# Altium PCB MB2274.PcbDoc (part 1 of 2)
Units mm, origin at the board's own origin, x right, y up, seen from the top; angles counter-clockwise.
Board outline 127 x 73 mm, 4 copper layers (Top Layer, Signal Layer 1, Signal Layer 2, Bottom Layer), stack 1.49 mm thick; 50 components, 79 nets, 284 pads, 1052 vias.
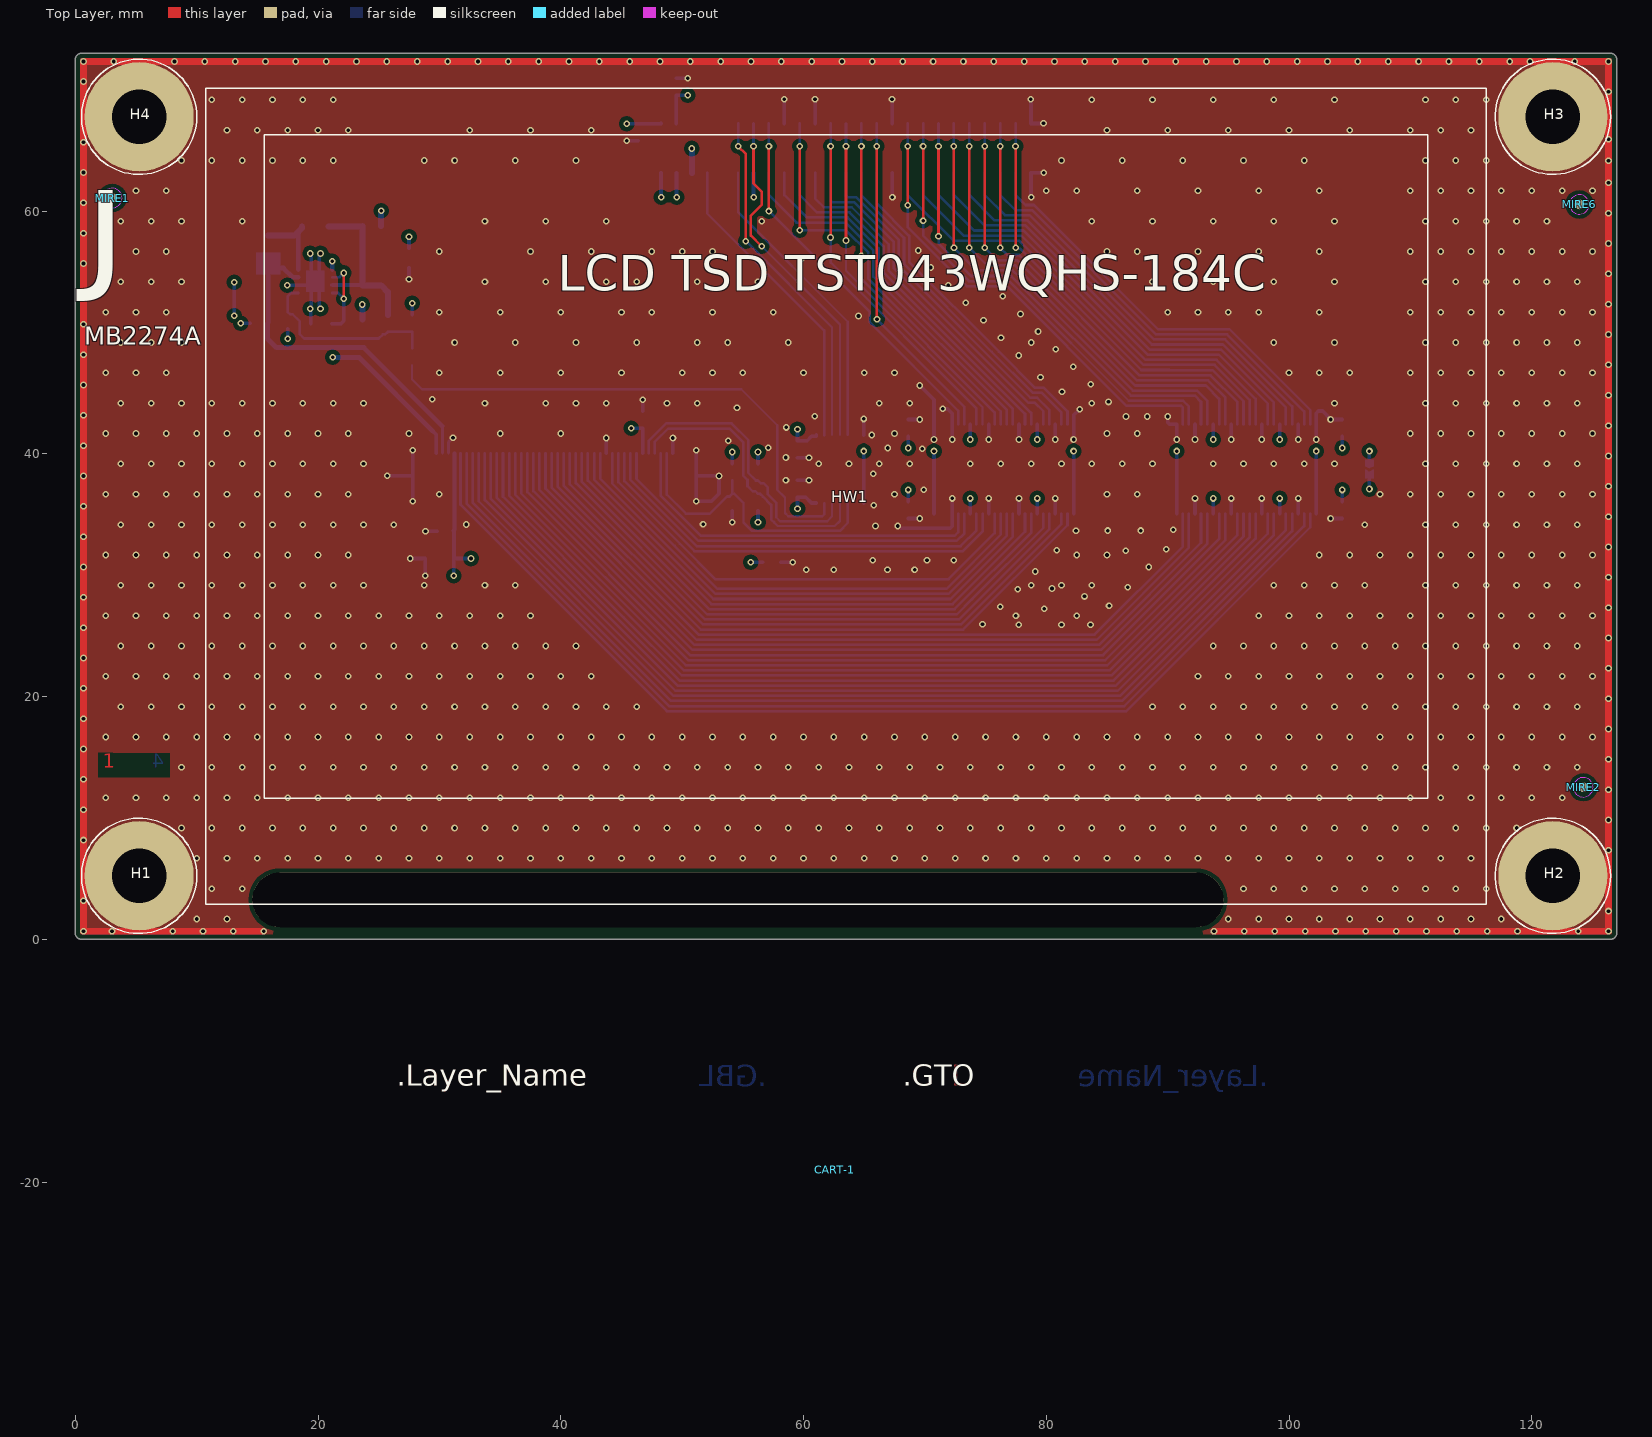
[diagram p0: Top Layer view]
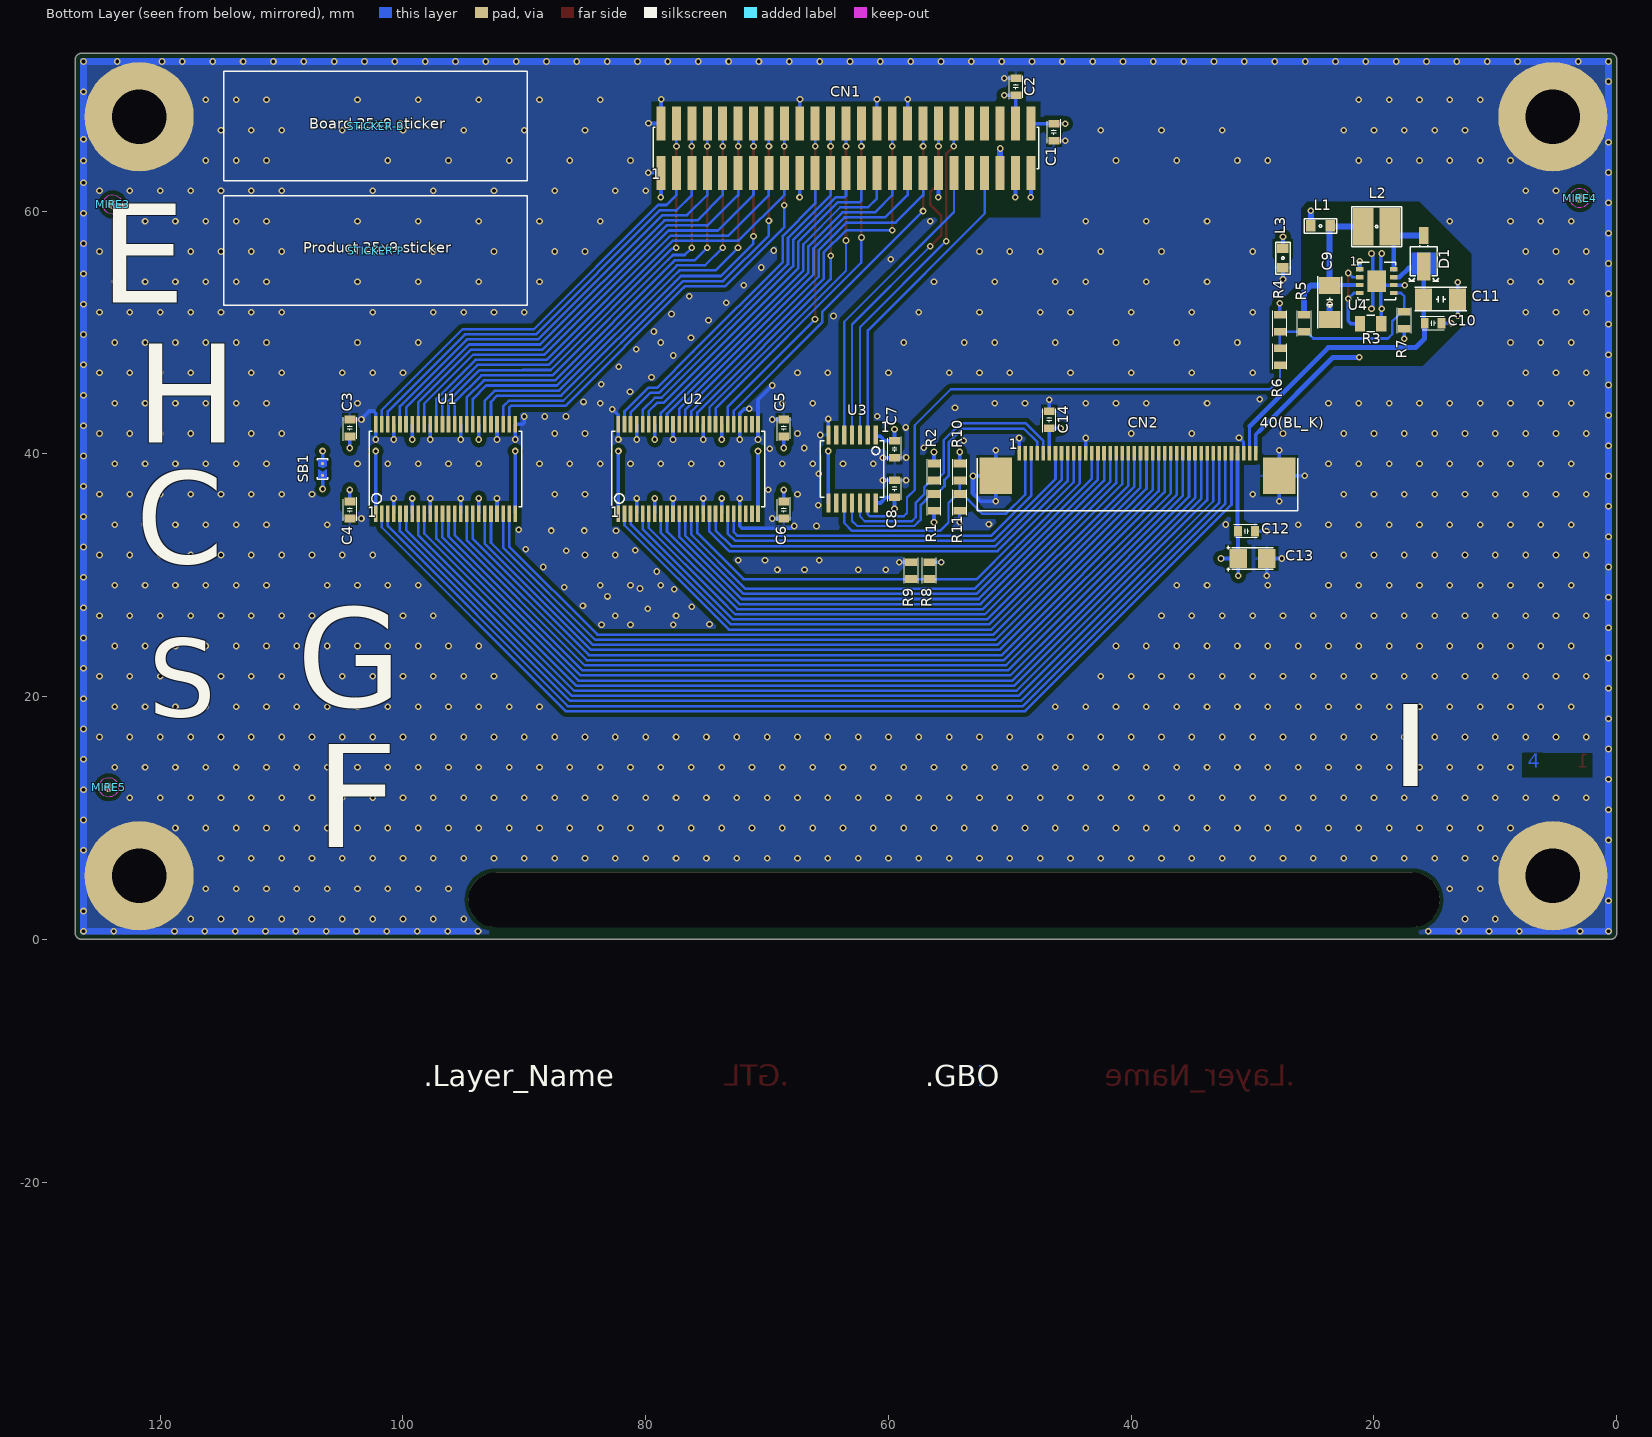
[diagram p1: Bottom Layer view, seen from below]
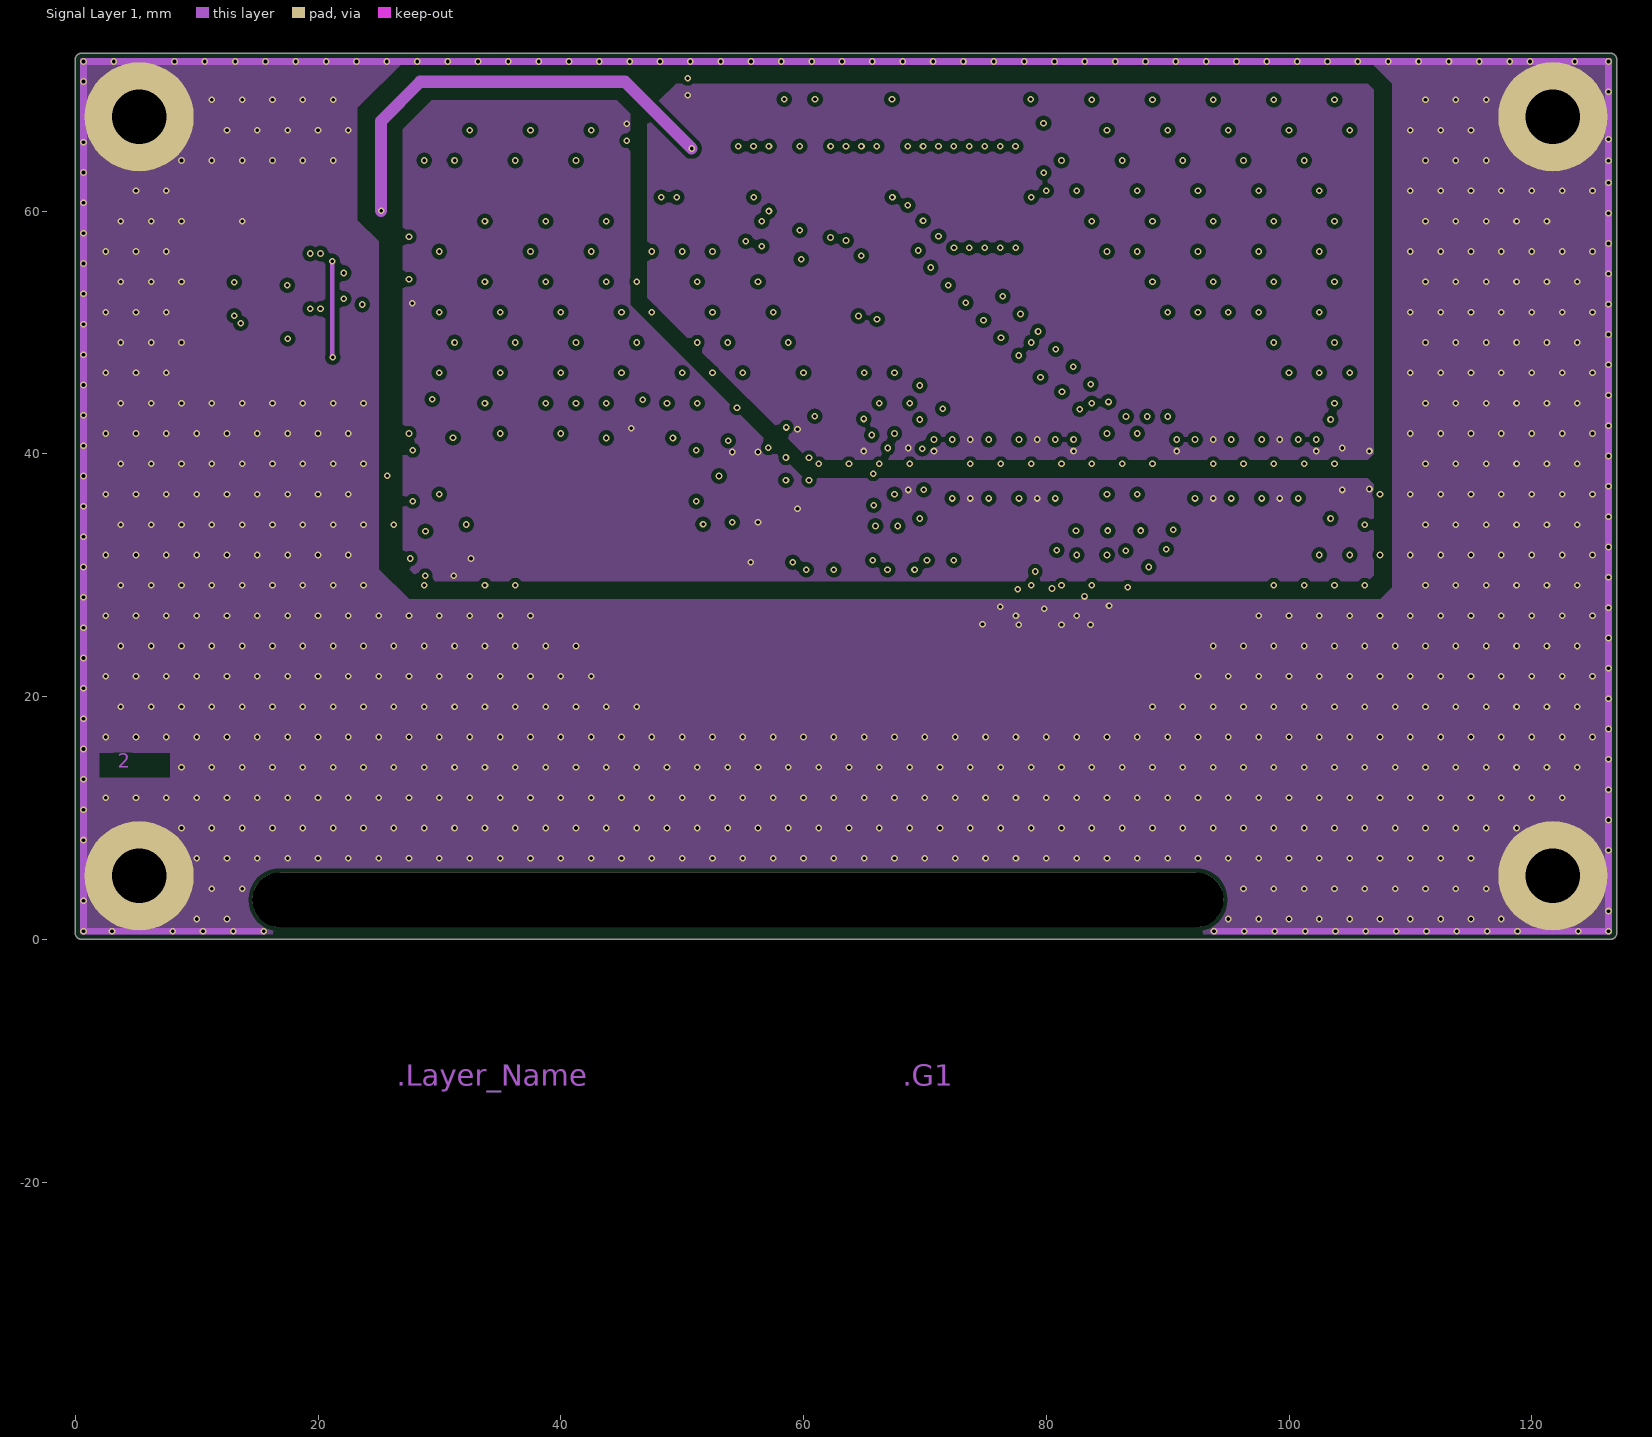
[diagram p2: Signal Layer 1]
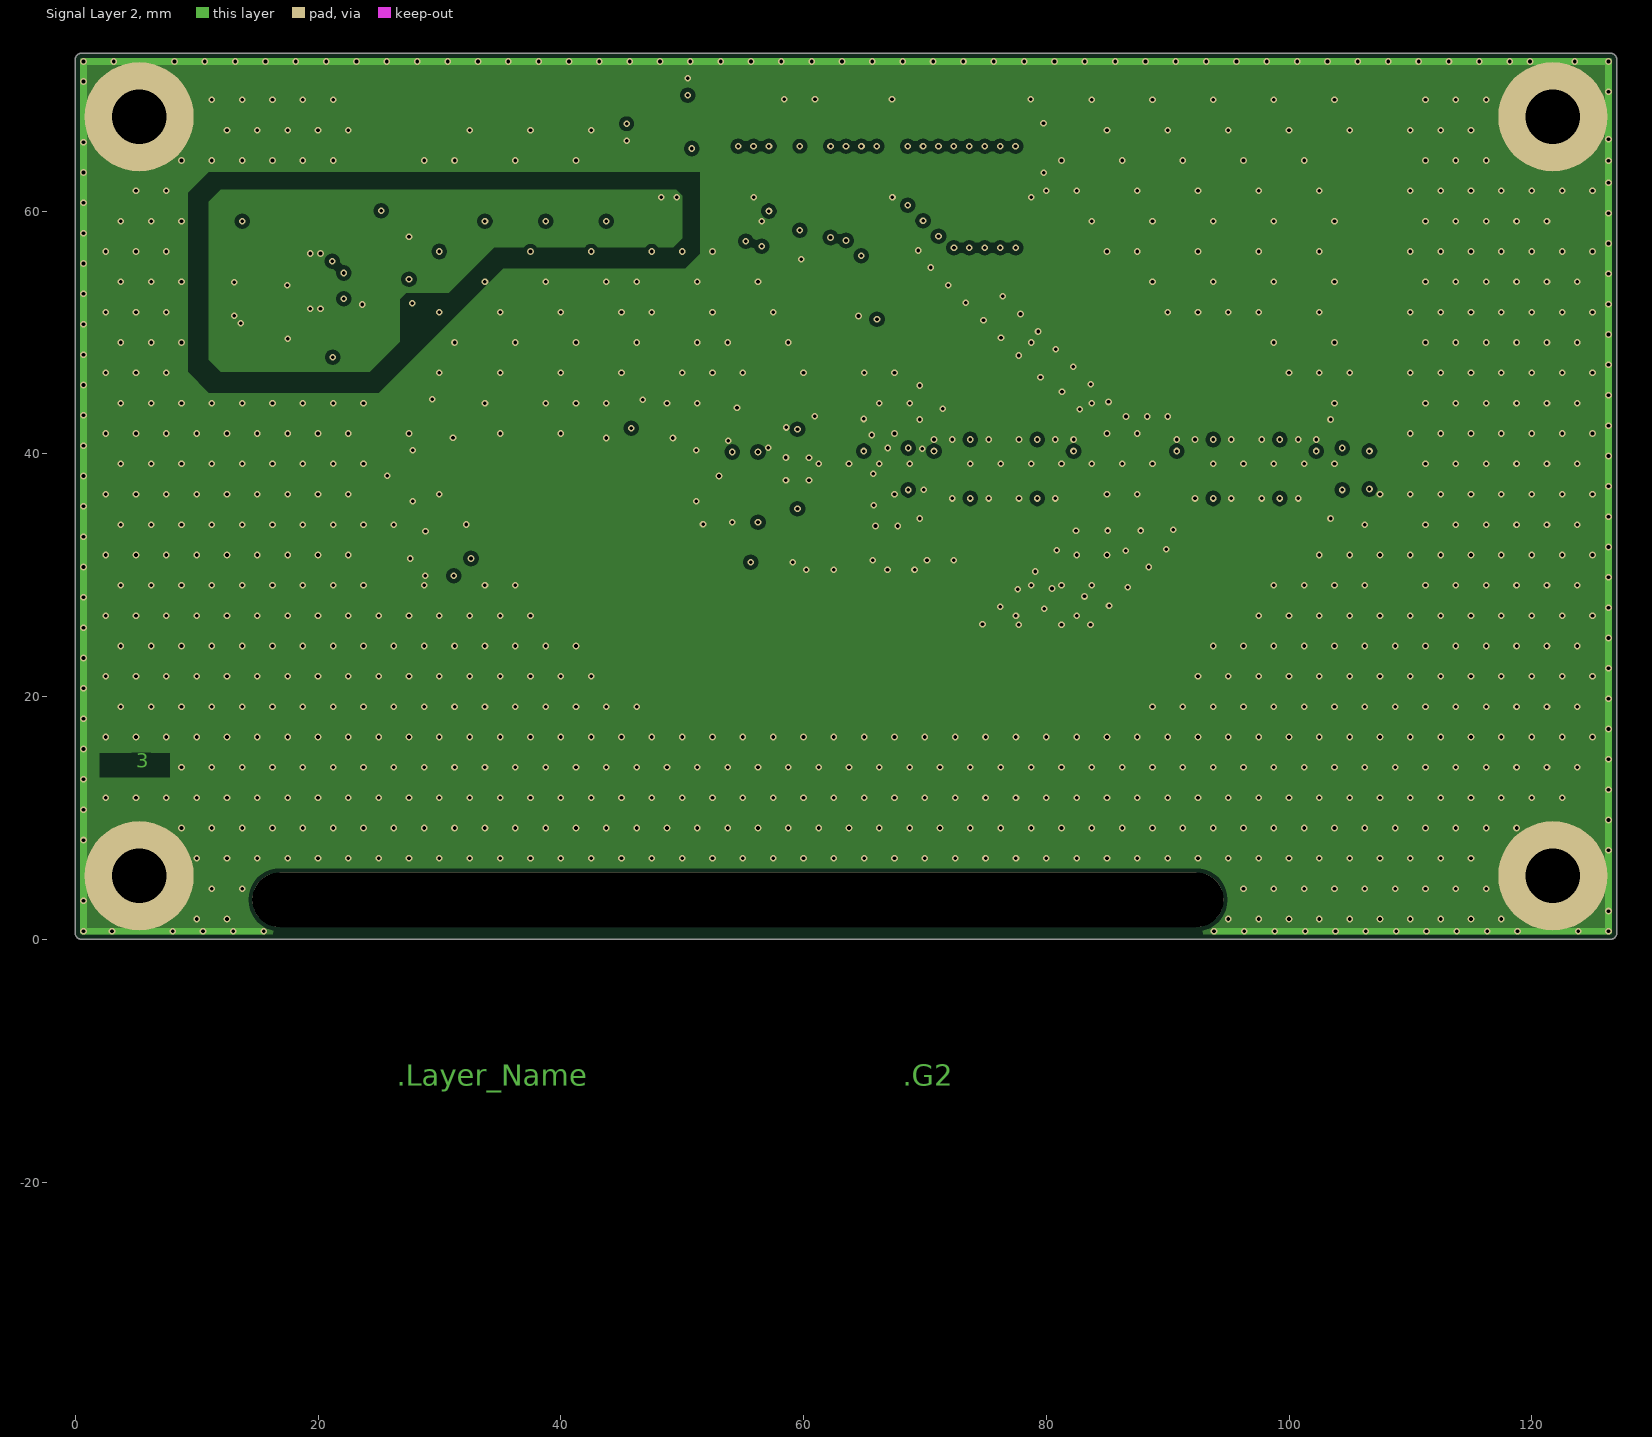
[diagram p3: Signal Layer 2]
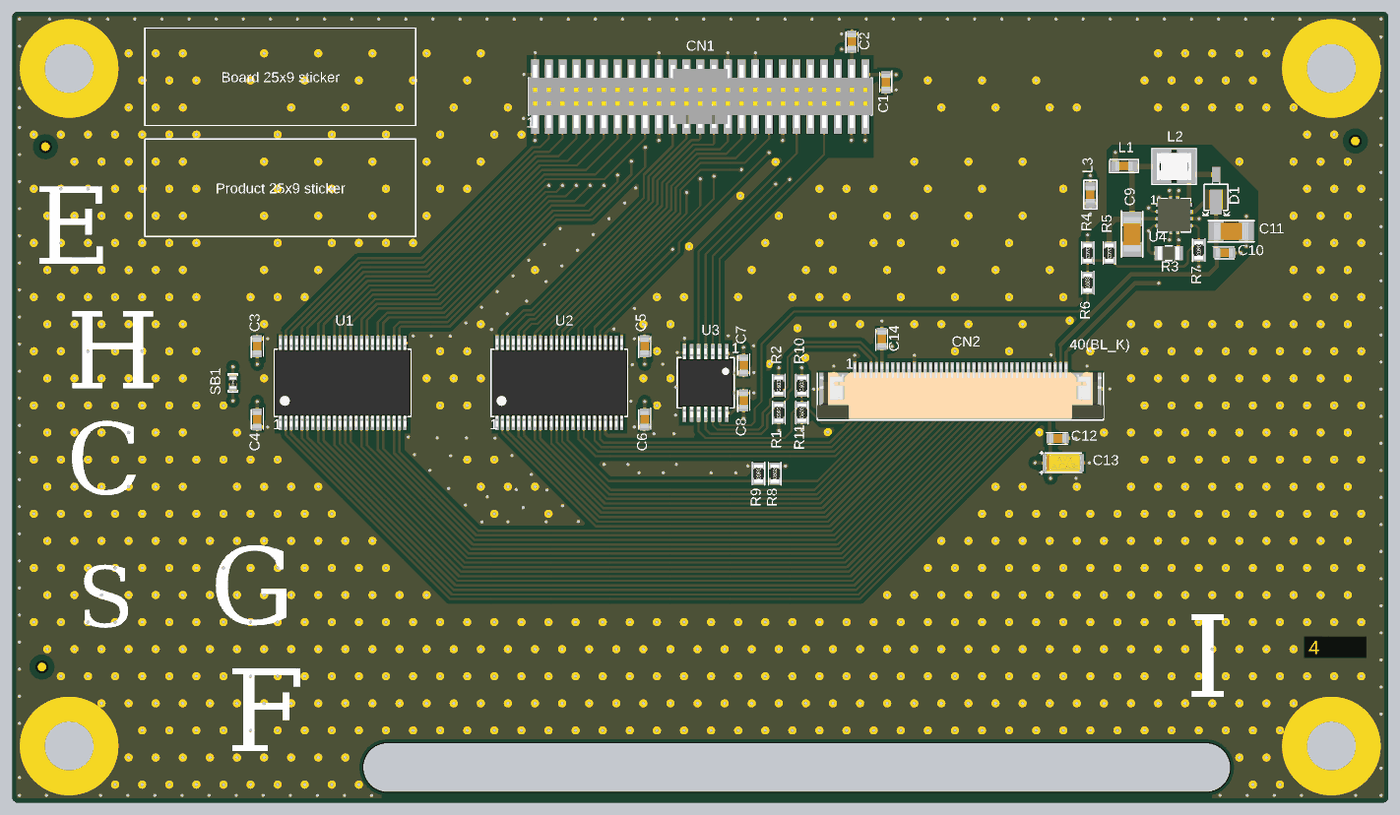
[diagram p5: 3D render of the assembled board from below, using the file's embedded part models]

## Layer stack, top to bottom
Top Solder: solder mask 0.15, Solder Resist, Dk 3.5
Top Layer: signal copper 0.035
Dielectric 1: prepreg 0.108, FR-4, Dk 3.8
Signal Layer 1: signal copper 0.035
Dielectric 2: core 1.134, FR-4, Dk 5.1
Signal Layer 2: signal copper 0.035
Dielectric 3: prepreg 0.108, FR-4, Dk 3.8
Bottom Layer: signal copper 0.035
Board Layer Stack Bottom Solder: solder mask 0.15, Solder Resist, Dk 3.5

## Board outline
0.5,0 cw(c0.5,0.5) 0,0.5 0,72.5 cw(c0.5,72.5) 0.5,73 126.5,73 cw(c126.5,72.5) 127,72.5 127,0.5 cw(c126.5,0.5) 126.5,0

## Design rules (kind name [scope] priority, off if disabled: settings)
BoardOutlineClearance [All] p1: gap=0.4 ignorepadtopadclearanceinfootprint=FALSE
Clearance Clearance_Default_same-net [All] p1: gap=0.21 ignorepadtopadclearanceinfootprint=TRUE except(0: Track-THPad THPad-Via; 0.2: Track-SMDPad Track-Region; 0.35: Arc-Poly Track-Poly SMDPad-Poly THPad-Poly Via-Poly Fill-Poly Poly-Poly Poly-Region Poly-Text Poly-Hole)
Clearance Clearance_Default [All] p2: gap=0.21 ignorepadtopadclearanceinfootprint=TRUE except(0.195: Track-SMDPad; 0.35: Arc-Poly Track-Poly SMDPad-Poly THPad-Poly Via-Poly Fill-Poly Poly-Poly Poly-Region Poly-Text Poly-Hole)
ComponentClearance [HasFootprint('TP_SMD_0-6MM') vs HasFootprint('TP_SMD_0-6MM')] p1: gap=1 collisioncheckmode=3 verticalgap=1 showdistances=FALSE
DiffPairsRouting [All] p1: maxlimit=0.254 minlimit=0.254 mostfreqgap=0.254 toplayer_minwidth=0.381 toplayer_maxwidth=0.381 toplayer_prefwidth=0.381 midlayer1_minwidth=0.381 midlayer1_maxwidth=0.381 midlayer1_prefwidth=0.381 midlayer2_minwidth=0.381 midlayer2_maxwidth=0.381 midlayer2_prefwidth=0.381 bottomlayer_minwidth=0.381 bottomlayer_maxwidth=0.381 bottomlayer_prefwidth=0.381 substack1={2C77A291-11D5-43C1-AB31-C92959FB7931} toplayer_{2c77a291-11d5-43c1-ab31-c92959fb7931}_minwidth=0.381 toplayer_{2c77a291-11d5-43c1-ab31-c92959fb7931}_maxwidth=0.381 toplayer_{2c77a291-11d5-43c1-ab31-c92959fb7931}_prefwidth=0.381 midlayer1_{2c77a291-11d5-43c1-ab31-c92959fb7931}_minwidth=0.381 midlayer1_{2c77a291-11d5-43c1-ab31-c92959fb7931}_maxwidth=0.381 midlayer1_{2c77a291-11d5-43c1-ab31-c92959fb7931}_prefwidth=0.381 midlayer2_{2c77a291-11d5-43c1-ab31-c92959fb7931}_minwidth=0.381 midlayer2_{2c77a291-11d5-43c1-ab31-c92959fb7931}_maxwidth=0.381 midlayer2_{2c77a291-11d5-43c1-ab31-c92959fb7931}_prefwidth=0.381 bottomlayer_{2c77a291-11d5-43c1-ab31-c92959fb7931}_minwidth=0.381 bottomlayer_{2c77a291-11d5-43c1-ab31-c92959fb7931}_maxwidth=0.381 bottomlayer_{2c77a291-11d5-43c1-ab31-c92959fb7931}_prefwidth=0.381 maxuncoupledlength=12.7
HoleSize [All] p1: absolutevalues=TRUE maxlimit=100 minlimit=0.025 maxpercent=80.000 minpercent=20.000
HoleToHoleClearance HoleToHoleClearance_Footprint [IsPad vs ispad] p1: gap=0.25 allowstackedmicrovias=TRUE
HoleToHoleClearance HoleToHoleClearance_STLINK [WithinRoom('RoomDefinition_STLINK')and TouchesRoom('RoomDefinition_STLINK')] p2: gap=0.25 allowstackedmicrovias=TRUE
HoleToHoleClearance [All] p3: gap=0.45 allowstackedmicrovias=TRUE
MinimumSolderMaskSliver [All] p1: minsoldermaskwidth=0.013
PlaneConnect [All] p1: planeconnectstyle=Relief reliefexpansion=0.508 reliefentries=4 reliefconductorwidth=0.254 reliefairgap=0.152
PolygonConnect [All] p1: thpad.connectstyle=Relief thpad.reliefconductorwidth=0.25 thpad.reliefentries=4 thpad.polygonreliefangle="90 Angle" thpad.airgapwidth=0.2 smdpad.connectstyle=Relief smdpad.reliefconductorwidth=0.25 smdpad.reliefentries=4 smdpad.polygonreliefangle="90 Angle" smdpad.airgapwidth=0.2 via.connectstyle=Direct via.reliefconductorwidth=0.25 via.reliefentries=4 via.polygonreliefangle="90 Angle" via.airgapwidth=0.2
RoutingVias RoutingVias_Default [All] p1: holewidth=0.35 width=0.55 viastyle="Through Hole" minholewidth=0.35 minwidth=0.55 maxholewidth=0.35 maxwidth=0.55 useviatemplates=TRUE viatemplateguid#1={86A10B8F-1ED7-42D9-8135-3F0C4B7C3344} viatemplatename#1=v55h30m40
ShortCircuit ShortCircuit_LNK [InComponentClass('LNK') vs InComponentClass('LNK')] p1: allowed=TRUE
ShortCircuit [All] p2: allowed=FALSE
SilkToSilkClearance [All] p1: silktosilkclearance=0.013
SilkToSolderMaskClearance [IsPad] p1: minsilkscreentomaskgap=0.013 clearancetoexposedcopper=TRUE
SolderMaskExpansion [All] p1: expansion=0.102 istentingtop=FALSE
SupplyNets "Schematic Supply Nets_4" [InNet('GND')] p1: voltage=0.000
SupplyNets "Schematic Supply Nets_3" [InNet('VDD')] p2: voltage=0.000
SupplyNets "Schematic Supply Nets_2" [InNet('BLGND')] p3: voltage=0.000
SupplyNets "Schematic Supply Nets_1" [InNet('BLVDD')] p4: voltage=0.000
SupplyNets "Schematic Supply Nets" [InNet('+3V3')] p5: voltage=0.000
Width Width_ALIMS [InNetClass('NC__ALIMS')] p1: maxlimit=10 minlimit=0.19 preferedwidth=0.3 substack1={2C77A291-11D5-43C1-AB31-C92959FB7931} toplayer_{2c77a291-11d5-43c1-ab31-c92959fb7931}_minwidth=0.089 toplayer_{2c77a291-11d5-43c1-ab31-c92959fb7931}_maxwidth=1.016 toplayer_{2c77a291-11d5-43c1-ab31-c92959fb7931}_prefwidth=0.254 midlayer1_{2c77a291-11d5-43c1-ab31-c92959fb7931}_minwidth=0.089 midlayer1_{2c77a291-11d5-43c1-ab31-c92959fb7931}_maxwidth=1.016 midlayer1_{2c77a291-11d5-43c1-ab31-c92959fb7931}_prefwidth=0.254 midlayer2_{2c77a291-11d5-43c1-ab31-c92959fb7931}_minwidth=0.089 midlayer2_{2c77a291-11d5-43c1-ab31-c92959fb7931}_maxwidth=1.016 midlayer2_{2c77a291-11d5-43c1-ab31-c92959fb7931}_prefwidth=0.254 bottomlayer_{2c77a291-11d5-43c1-ab31-c92959fb7931}_minwidth=0.089 bottomlayer_{2c77a291-11d5-43c1-ab31-c92959fb7931}_maxwidth=1.016 bottomlayer_{2c77a291-11d5-43c1-ab31-c92959fb7931}_prefwidth=0.254
Width Width_Default [All] p2: maxlimit=10 minlimit=0.19 preferedwidth=0.21 substack1={2C77A291-11D5-43C1-AB31-C92959FB7931} toplayer_{2c77a291-11d5-43c1-ab31-c92959fb7931}_minwidth=0.089 toplayer_{2c77a291-11d5-43c1-ab31-c92959fb7931}_maxwidth=1.016 toplayer_{2c77a291-11d5-43c1-ab31-c92959fb7931}_prefwidth=0.254 midlayer1_{2c77a291-11d5-43c1-ab31-c92959fb7931}_minwidth=0.089 midlayer1_{2c77a291-11d5-43c1-ab31-c92959fb7931}_maxwidth=1.016 midlayer1_{2c77a291-11d5-43c1-ab31-c92959fb7931}_prefwidth=0.254 midlayer2_{2c77a291-11d5-43c1-ab31-c92959fb7931}_minwidth=0.089 midlayer2_{2c77a291-11d5-43c1-ab31-c92959fb7931}_maxwidth=1.016 midlayer2_{2c77a291-11d5-43c1-ab31-c92959fb7931}_prefwidth=0.254 bottomlayer_{2c77a291-11d5-43c1-ab31-c92959fb7931}_minwidth=0.089 bottomlayer_{2c77a291-11d5-43c1-ab31-c92959fb7931}_maxwidth=1.016 bottomlayer_{2c77a291-11d5-43c1-ab31-c92959fb7931}_prefwidth=0.254
21 further rules are at their usual default settings.

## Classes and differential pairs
net class NC__ALIMS: +3V3 BLGND BLVDD VDD
component class "Level Shifter": C3 C4 C5 C6 C7 C8 R1 R2 SB1 U1 U2 U3
component class LCD: C9 C10 C11 C12 C13 C14 CN2 D1 L1 L2 L3 R3 R4 R5 R6 R7 R8 R9 R10 R11 U4
component class Host: C1 C2 CN1

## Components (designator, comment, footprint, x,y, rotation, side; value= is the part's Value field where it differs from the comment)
C1 "100nF" C0603 46.375,66.5 r90 bottom
C2 "100nF" C0603 49.5,70.25 r270 bottom
C3 "100nF" C0603 104.375,42.125 r270 bottom
C4 "100nF" C0603 104.375,35.375 r90 bottom
C5 "100nF" C0603 68.625,42.125 r270 bottom
C6 "100nF" C0603 68.625,35.375 r90 bottom
C7 "100nF" C0603 59.5,40.375 r90 bottom
C8 "100nF" C0603 59.5,37.125 r270 bottom
C9 "Capacitor" C1206_H1P25 23.65,52.475 r90 bottom value=4.7uF
C10 "Capacitor" C0603 15.125,50.75 r0 bottom value=100nF
C11 "Capacitor" C1206_H1P25 14.5,52.75 r0 bottom value=4.7uF
C12 "Capacitor" C0603 30.5,33.625 r0 bottom value=100nF
C13 "Cap_POL_TANA" CPOL_TAJ-A_1206_H180 30,31.375 r180 bottom value=4.7uF
C14 "Capacitor" C0603 46.75,42.813 r270 bottom value=100nF
CART-1 "Comment" Sheetbox_4L2S 17.483,-24.352 r0 top
CN1 "Header 25x2 LCD MODULE" CON_SAMTEC_FTSH-125-01-F-DV-K 63.5,65.182 r180 bottom locked value="Header 25x2"
CN2 "68714014022" CON_WE_68714014022 39.49,39.12 r180 bottom locked value=Socket_FFC/FPC_68714014022
D1 "STPS1L40M" DIO_DO216-AA 15.9,56.475 r90 bottom
H1 "POSITION HOLE" PTH_450_900 5.26,5.23 r0 top locked
H2 "POSITION HOLE" PTH_450_900 121.74,5.23 r0 top locked
H3 "POSITION HOLE" PTH_450_900 121.74,67.77 r0 top locked
H4 "POSITION HOLE" PTH_450_900 5.26,67.77 r0 top locked
HW1 "Comment" LCD_DRAWING_TSD-TST043WQHS-184C 63.5,36.5 r0 top locked
L1 "BEAD" L0603 24.4,58.775 r180 bottom value="600R @ 100MHz"
L2 "Inductor" L1210_LQH 19.775,58.725 r180 bottom value=4.7uH
L3 "BEAD" L0603 27.5,56.125 r90 bottom value="600R @ 100MHz"
MIRE1 "Comment" MIRE_PLACE_SMD_0P8MM 3.05,61.075 r180 top
MIRE2 "Comment" MIRE_PLACE_SMD_0P8MM 124.25,12.525 r180 top
MIRE3 "Comment" MIRE_PLACE_SMD_0P8MM 123.925,60.55 r0 bottom
MIRE4 "Comment" MIRE_PLACE_SMD_0P8MM 3.05,61.075 r0 bottom
MIRE5 "Comment" MIRE_PLACE_SMD_0P8MM 124.25,12.525 r0 bottom
MIRE6 "Comment" MIRE_PLACE_SMD_0P8MM 123.925,60.55 r180 top
R1 "4K7" R0603 56.25,36 r270 bottom
R2 "4K7" R0603 56.25,38.5 r90 bottom
R3 "Resistor" R0805_H0P5 20.275,50.725 r0 bottom value=6R2
R4 "Resistor" R0603 27.75,50.75 r270 bottom value=4K7
R5 "Resistor" R0603 25.75,50.75 r270 bottom value=4K7
R6 "Resistor" R0603 27.75,48 r90 bottom value=0R
R7 "Resistor" R0603 17.5,51 r270 bottom value=4K7
R8 "Resistor" R0603 56.625,30.375 r90 bottom value=4K7
R9 "Resistor" R0603 58.125,30.375 r270 bottom value=4K7
R10 "Resistor" R0603 54.125,38.5 r90 bottom value=220K
R11 "Resistor" R0603 54.125,36 r90 bottom value=220K
SB1 "SB_ON" SOLDER-BRIDGE_R0402-0R 106.625,38.75 r270 bottom value=0R
STICKER-B "Comment" STICKER_BOARD_25X9 102.25,67 r180 bottom
STICKER-P "Comment" STICKER_PRODUCT_25X9 102.25,56.75 r180 bottom
U1 "SN74LVC16T245DGGR" ICC_TSSOP48_12P5X6P1_P050 96.5,38.75 r180 bottom
U2 "SN74LVC16T245DGGR" ICC_TSSOP48_12P5X6P1_P050 76.5,38.75 r180 bottom
U3 "TXS0104EPWR" ICC_TSSOP14_5X4P40_P065 63,38.75 r0 bottom
U4 "TPS61042DRB" ICC_VSON8-EPAD_3X3_P065 19.775,54.225 r180 bottom value=TPS61042DRBR

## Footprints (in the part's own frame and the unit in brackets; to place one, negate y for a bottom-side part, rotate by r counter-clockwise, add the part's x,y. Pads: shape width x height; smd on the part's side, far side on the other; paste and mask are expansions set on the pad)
C0603 [mm]
  rect 0.64x0.89 smd mask+0.05: 1(-0.7,0) 2(0.7,0)
  silkscreen extent -0.9,-0.55 1.05,0.55, body extent -0.9,-0.5 0.9,0.5, height 1.4
C1206_H1P25 [mm]
  rect 1.4x1.78 smd mask+0.05: 1(-1.4,0) 2(1.4,0)
  silkscreen extent -2.12,-0.97 2.15,0.97, body extent -1.7,-0.9 1.7,0.9, height 1.45
CON_SAMTEC_FTSH-125-01-F-DV-K [mm]
  rect 0.74x2.79 smd mask+0.05: 1(-15.24,-2.035) 2(-15.24,2.035) 3(-13.97,-2.035) 4(-13.97,2.035) 5(-12.7,-2.035) 6(-12.7,2.035) 7(-11.43,-2.035) 8(-11.43,2.035) 9(-10.16,-2.035) 10(-10.16,2.035) 11(-8.89,-2.035) 12(-8.89,2.035) 13(-7.62,-2.035) 14(-7.62,2.035) 15(-6.35,-2.035) 16(-6.35,2.035) 17(-5.08,-2.035) 18(-5.08,2.035) 19(-3.81,-2.035) 20(-3.81,2.035) 21(-2.54,-2.035) 22(-2.54,2.035) 23(-1.27,-2.035) 24(-1.27,2.035) 25(0,-2.035) 26(0,2.035) 27(1.27,-2.035) 28(1.27,2.035) 29(2.54,-2.035) 30(2.54,2.035) 31(3.81,-2.035) 32(3.81,2.035) 33(5.08,-2.035) 34(5.08,2.035) 35(6.35,-2.035) 36(6.35,2.035) 37(7.62,-2.035) 38(7.62,2.035) 39(8.89,-2.035) 40(8.89,2.035) 41(10.16,-2.035) 42(10.16,2.035) 43(11.43,-2.035) 44(11.43,2.035) 45(12.7,-2.035) 46(12.7,2.035) 47(13.97,-2.035) 48(13.97,2.035) 49(15.24,-2.035) 50(15.24,2.035)
  silkscreen extent -15.88,-1.71 15.88,1.71, body extent -15.88,-2.92 15.88,2.92, height 6.12
CON_WE_68714014022 [mm] "MCD-027xx"
  rect 0.3x1.2 smd mask+0.05: 1(-9.75,0.93) 2(-9.25,0.93) 3(-8.75,0.93) 4(-8.25,0.93) 5(-7.75,0.93) 6(-7.25,0.93) 7(-6.75,0.93) 8(-6.25,0.93) 9(-5.75,0.93) 10(-5.25,0.93) 11(-4.75,0.93) 12(-4.25,0.93) 13(-3.75,0.93) 14(-3.25,0.93) 15(-2.75,0.93) 16(-2.25,0.93) 17(-1.75,0.93) 18(-1.25,0.93) 19(-0.75,0.93) 20(-0.25,0.93) 21(0.25,0.93) 22(0.75,0.93) 23(1.25,0.93) 24(1.75,0.93) 25(2.25,0.93) 26(2.75,0.93) 27(3.25,0.93) 28(3.75,0.93) 29(4.25,0.93) 30(4.75,0.93) 31(5.25,0.93) 32(5.75,0.93) 33(6.25,0.93) 34(6.75,0.93) 35(7.25,0.93) 36(7.75,0.93) 37(8.25,0.93) 38(8.75,0.93) 39(9.25,0.93) 40(9.75,0.93)
  rect 2.7x3 smd mask+0.05: MP1(-11.68,-0.93) MP2(11.68,-0.93)
  silkscreen extent -13.2,-3.8 13.2,0.52, body extent -13.2,-3.7 13.2,1.4, height 2.15
CPOL_TAJ-A_1206_H180 [mm]
  rect 1.45x1.6 smd mask+0.05: 1(-1.175,0) 2(1.175,0)
  silkscreen extent -2.15,-1.05 1.7,1.05, body extent -1.7,-0.9 1.7,0.9, height 1.8
DIO_DO216-AA [mm]
  rect 1.38x0.75 smd mask+0.05: 1(1.515,0)
  rect 2.32x1.1 smd mask+0.05: 2(-1.045,0)
  Top Layer region: -1.705,1.015 0.115,1.015 0.115,-1.015 -1.705,-1.015
  silkscreen extent -2.25,-1.22 0.72,1.22, body extent -2.02,-1.02 1.83,1.02, height 1.15
ICC_TSSOP14_5X4P40_P065 [mm]
  rect 0.35x1.6 smd mask+0.05: 1(-1.95,-2.8) 2(-1.3,-2.8) 3(-0.65,-2.8) 4(0,-2.8) 5(0.65,-2.8) 6(1.3,-2.8) 7(1.95,-2.8) 8(1.95,2.8) 9(1.3,2.8) 10(0.65,2.8) 11(0,2.8) 12(-0.65,2.8) 13(-1.3,2.8) 14(-1.95,2.8)
  silkscreen extent -2.63,-2.32 2.63,2.32, body extent -2.55,-3.2 2.55,3.2, height 1.21
ICC_TSSOP48_12P5X6P1_P050 [mm]
  rect 0.3x1.35 smd mask+0.05: 1(-5.75,-3.675) 2(-5.25,-3.675) 3(-4.75,-3.675) 4(-4.25,-3.675) 5(-3.75,-3.675) 6(-3.25,-3.675) 7(-2.75,-3.675) 8(-2.25,-3.675) 9(-1.75,-3.675) 10(-1.25,-3.675) 11(-0.75,-3.675) 12(-0.25,-3.675) 13(0.25,-3.675) 14(0.75,-3.675) 15(1.25,-3.675) 16(1.75,-3.675) 17(2.25,-3.675) 18(2.75,-3.675) 19(3.25,-3.675) 20(3.75,-3.675) 21(4.25,-3.675) 22(4.75,-3.675) 23(5.25,-3.675) 24(5.75,-3.675) 25(5.75,3.675) 26(5.25,3.675) 27(4.75,3.675) 28(4.25,3.675) 29(3.75,3.675) 30(3.25,3.675) 31(2.75,3.675) 32(2.25,3.675) 33(1.75,3.675) 34(1.25,3.675) 35(0.75,3.675) 36(0.25,3.675) 37(-0.25,3.675) 38(-0.75,3.675) 39(-1.25,3.675) 40(-1.75,3.675) 41(-2.25,3.675) 42(-2.75,3.675) 43(-3.25,3.675) 44(-3.75,3.675) 45(-4.25,3.675) 46(-4.75,3.675) 47(-5.25,3.675) 48(-5.75,3.675)
  silkscreen extent -6.3,-3.1 6.3,3.1, body extent -6.3,-4.05 6.3,4.05, height 1.2
ICC_VSON8-EPAD_3X3_P065 [mm] "MCD-02727"
  rect 0.6x0.35 smd paste+0 mask+0.05: 1(-1.4,0.975) 2(-1.4,0.325) 3(-1.4,-0.325) 4(-1.4,-0.975) 5(1.4,-0.975) 6(1.4,-0.325) 7(1.4,0.325) 8(1.4,0.975)
  rect 1.5x1.75 smd paste+0 mask+0.05: 9(0,0)
  Top Layer region: -0.75,0.875 -0.45,0.875 -0.45,1.7 -0.45,1.7 -0.2,1.7 -0.2,0.875 0.2,0.875 0.2,1.7 0.2,1.7 0.45,1.7 0.45,0.875 0.75,0.875 0.75,-0.875 0.45,-0.875 0.45,-1.7 0.45,-1.7 0.2,-1.7 0.2,-0.875 -0.2,-0.875 -0.2,-1.7 -0.2,-1.7 -0.45,-1.7 -0.45,-0.875 -0.45,-0.875 -0.75,-0.875
  silkscreen extent -1.55,-1.55 1.55,1.55, body extent -1.5,-1.5 1.5,1.5, height 1
L0603 [mm]
  rect 0.8x0.95 smd mask+0.05: 1(-0.8,0) 2(0.8,0)
  silkscreen extent -1.33,-0.6 1.33,0.6, body extent -0.87,-0.47 0.87,0.47, height 0.95
L1210_LQH [mm]
  rect 1.7x3.1 smd mask+0.05: 1(-1.1,0) 2(1.1,0)
  silkscreen extent -2.05,-1.65 2.05,1.65, body extent -1.75,-1.36 1.75,1.36, height 2
LCD_DRAWING_TSD-TST043WQHS-184C [mm] "MCD-XXXXX"
  silkscreen extent -52.75,-33.6 52.75,33.6, body extent -52.75,-34.64 52.75,33.6, height 5.58
MIRE_PLACE_SMD_0P8MM [mm]
  round 0.8 smd paste-10 mask+0.2: 1(0,0)
  Top Layer keep-out circle w0.01: c0,0 r0.804
PTH_450_900 [mm] "MCD-01612"
  round 9 hole 4.5 mask+0.05: 1(0,0)
  silkscreen extent -4.75,-4.75 4.75,4.75
R0603 [mm]
  rect 0.64x1 smd mask+0.05: 1(-0.7,0) 2(0.7,0)
  silkscreen extent -1.05,-0.58 1.05,0.58, body extent -0.9,-0.5 0.9,0.5, height 0.56
R0805_H0P5 [mm] "MCD-01537"
  rect 0.85x1.3 smd mask+0.05: 1(-0.875,0) 2(0.875,0)
  silkscreen extent -0.33,-0.67 0.33,0.67, body extent -1.05,-0.68 1.05,0.68, height 0.6
Sheetbox_4L2S [mil] "Sheetbox 4 layers / 2 silkscreens"
  round 20 on Mech16: 1(813.78,210.69) 1(2736.9,210.69)
SOLDER-BRIDGE_R0402-0R [mil] "MCD-01619"
  round 10 smd paste-393.7: 1(-17.72,0) 2(20.67,0)
  Top Layer region: -30.51,-13.78 -30.51,13.78 -8.86,13.78 -2.95,0 -8.86,-13.78
  Top Layer region: 1.48,13.78 8.37,0 1.48,-13.78 30.51,-13.78 30.51,13.78
  silkscreen extent -33,-17 33,17, body extent -20,-12 20,12, height 14
STICKER_BOARD_25X9 [mm] "MCD-00235"
  silkscreen extent -12.5,-4.5 12.5,4.5
STICKER_PRODUCT_25X9 [mm] "MCD-00547"
  silkscreen extent -12.5,-4.5 12.5,4.5

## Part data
C1 C2 C3 C4 C5 C6 C7 C8 C12 C14: library part MCD-00211, "Capacitor, MLCC, 100nF, 16V, X7R, +/-10%, 0603, T=0.8mm", Manufacturer=YAGEO, Manufacturer_Part_Number=CC0603KRX7R7BB104, Package=0603
C9 C11: library part MCD-00013, "Capacitor, MLCC, 4.7uF, 50V, X7R, +/-10%, 1206, T=1.27mm", Manufacturer=AVX, Manufacturer_Part_Number=12065C475KAT2A, Package=1206
C10: library part MCD-01099, "Capacitor, MLCC, 100nF, 50V, X7R, +/-10%, 0603, T=0.8mm", Manufacturer=YAGEO, Manufacturer_Part_Number=CC0603KRX7R9BB104, Package=0603
C13: library part MCD-00007, "Capacitor, Tantalum, 4.7uF, 16V, 4R, +/-10%, 3216, T=1.6mm", Manufacturer=AVX, Manufacturer_Part_Number=TAJA475K016R, Package="3216 (metric)"
CN1: library part MCD-01187, "Header, 25x2, 1.27mm, VR, SMD, T=5.97mm", Manufacturer=SAMTEC, Manufacturer_Part_Number=FTSH-125-01-F-DV-K
CN2: library part MCD-02724, "Socket_FFC/FPC, 40pins, 0.5mm, RA, SMD, T=2.1mm", Manufacturer="WURTH ELEKTRONIK"
D1: library part MCD-00033, "Diode, Schottky, 0V46, 1A, 40V, DO216-AA", Manufacturer=STMICROELECTRONICS, Manufacturer_HQ_COO=EU, Package=DO216-AA
H1 H2 H3 H4: library part MCD-01612, "POSITION HOLE C9D4R5", Manufacturer=N/A
L1 L3: library part MCD-00047, "Ferrite bead, 600R @1 00MHz, +/-25%, 350mA, 0R5, 0603, T=0.8mm", Manufacturer=TAI-TECH, Manufacturer_Part_Number=FCM1608KF-601T03, Package=0603
L2: library part MCD-00048, "Inductor, 4.7uH, +/-30%, 1A, 180mR, 1210, T=1.7mm", Manufacturer=MURATA, Manufacturer_Part_Number=LQH32PN4R7NN0L, Package=1210
R1 R2 R4 R5 R7 R8 R9: library part MCD-00219, "Resistor, 4K7, 0603, +/-1%, 1/10W", Manufacturer=YAGEO, Manufacturer_Part_Number=RC0603FR-074K7L, Package=0603
R3: library part MCD-02728, "Resistor, 6R2, 0805, +/-1%, 1/8W", Manufacturer=YAGEO, Manufacturer_Part_Number=RC0805FR-076R2L, Package=0805
R6: library part MCD-00056, "Resistor, 0R, 0603, +/-5%, 1/10W", Manufacturer=YAGEO, Manufacturer_Part_Number=RC0603JR-070RL, Package=0603
R10 R11: library part MCD-00347, "Resistor, 220K, 0603, +/-1%, 1/10W", Manufacturer=YAGEO, Manufacturer_Part_Number=RC0603FR-07220KL, Package=0603
SB1: library part MCD-01618, "Resistor, 0R, SB0402, 5%, 0.063W", Manufacturer=YAGEO, Manufacturer_Part_Number=RC0402JR-070RL, Package=0402
U1 U2: library part MCD-01074, "Bus Transceiver, 16-bit Dual-Supply bus transceiver with configurable Level-Shifting/Voltage translation and Tri-State outputs", Manufacturer="TEXAS INSTRUMENTS", Package=TSSOP-48
U3: library part MCD-00274, "Voltage Translator, 4-BIT bidirectional voltage-level translator for open-drain and PUSH-PULL applications", Manufacturer="TEXAS INSTRUMENTS", Package=TSSOP-PW-14
U4: library part MCD-02727, "LED driver, High frequency boost converter with constant current output", Manufacturer="TEXAS INSTRUMENTS", Manufacturer_Part_Number=TPS61042DRBR, Package=SON-8

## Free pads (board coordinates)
  oval 80x4.5 hole 4.5 slot 80 at 0 deg unplated: ""(54.6,3.25)

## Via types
v1: diameter 0.55, hole 0.3, Top Layer to Bottom Layer, 1052 vias

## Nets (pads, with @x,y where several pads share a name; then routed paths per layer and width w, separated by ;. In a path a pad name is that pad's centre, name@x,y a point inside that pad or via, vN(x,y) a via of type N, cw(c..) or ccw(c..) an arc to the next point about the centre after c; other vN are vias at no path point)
+3V3: C1.2 C4.2 C6.2 C8.2 C12.2 C13.1 C14.2 CN1.50 CN2.6 CN2.37 R1.2 R2.2 R4.1 R8.2 R10.2 SB1.2 U1.7 U1.18 U2.7 U2.18 U3.14 | length 33.1
  Bottom Layer w0.3: R4.1@27.75,51.45 v1(27.75,52.4) ; v1(31.175,29.95) C13.1@31.175,31.375 ; CN2.37@31.24,40.05 31.24,33.765 31.15,33.675 C12.2@31.2,33.625 31.2,31.4 C13.1@31.175,31.375 ; v1(32.6,31.375) C13.1@31.175,31.375 ; v1(45.425,67.2) C1.2@46.375,67.2 48.243,67.2 CN1.50@48.26,67.217 ; v1(45.8,42.112) C14.2@46.75,42.112 46.74,42.102 CN2.6@46.74,40.05 ; R10.2@54.125,39.2 v1(54.125,40.15) ; v1(55.64,31.075) R8.2@56.625,31.075 ; v1(56.25,34.35) R1.2@56.25,35.3 ; R2.2@56.25,39.2 v1(56.25,40.15) ; v1(59.5,35.475) C8.2@59.5,36.425 60.175,36.425 60.65,35.95 U3.14@61.05,35.95 ; C6.2@68.625,36.075 v1(68.625,37.025) ; U2.18@73.75,35.075 v1(73.75,36.325) ; U2.7@79.25,35.075 v1(79.25,36.325) ; U1.18@93.75,35.075 v1(93.75,36.325) ; U1.7@99.25,35.075 v1(99.25,36.325) ; C4.2@104.375,36.075 v1(104.375,37.025) ; v1(106.625,37.1) SB1.2@106.625,38.225 106.625,38.352
B0: CN2.20 U2.2 | length 54.2
  Bottom Layer w0.21: CN2.20@39.74,40.05 39.74,37.313 51.533,25.52 73.154,25.52 81.75,34.116 U2.2@81.75,35.075
B1: CN2.19 U2.3 | length 52.7
  Bottom Layer w0.21: CN2.19@40.24,40.05 40.24,37.407 51.707,25.94 72.98,25.94 81.25,34.21 U2.3@81.25,35.075
B2: CN2.18 U2.5 | length 51
  Bottom Layer w0.21: CN2.18@40.74,40.05 40.74,37.501 51.881,26.36 72.806,26.36 80.25,33.804 U2.5@80.25,35.075
B3: CN2.17 U2.6 | length 49.6
  Bottom Layer w0.21: CN2.17@41.24,40.05 41.24,37.595 52.055,26.78 72.632,26.78 73.891,28.04 79.75,33.898 U2.6@79.75,35.075
B4: CN2.16 U2.8 | length 47.9
  Bottom Layer w0.21: CN2.16@41.74,40.05 41.74,37.689 52.229,27.2 72.458,27.2 78.75,33.492 U2.8@78.75,35.075
B5: CN2.15 U2.9 | length 46.4
  Bottom Layer w0.21: CN2.15@42.24,40.05 42.24,37.783 52.403,27.62 72.284,27.62 78.25,33.586 U2.9@78.25,35.075
B6: CN2.14 U2.11 | length 44.8
  Bottom Layer w0.21: CN2.14@42.74,40.05 42.74,37.877 52.577,28.04 72.11,28.04 77.25,33.18 U2.11@77.25,35.075
B7: CN2.13 U2.12 | length 43.3
  Bottom Layer w0.21: CN2.13@43.24,40.05 43.24,37.971 52.751,28.46 71.936,28.46 76.75,33.274 U2.12@76.75,35.075
BL_A: C10.2 C11.2 CN2.39 D1.2 U4.7 | length 28.3
  Bottom Layer w0.25: CN2.39@30.24,40.05 30.24,42.285
  Bottom Layer w0.4: C10.2@15.825,50.75 15.825,49.5 16.575,48.75 23.775,48.75 30.24,42.285 ; C10.2@15.9,50.825 C11.2@15.9,52.75 D1.2@15.9,55.43 16.026,55.304 17.146,55.304 17.9,54.55 U4.7@18.375,54.55
BL_CTRL: R6.1 U3.13 | length 44.7
  Bottom Layer w0.19: R6.1@27.75,47.3 27.75,46.15 28.575,45.325 54.875,45.325 57.84,42.36 57.84,37.026 58.475,36.391 58.475,35.125 58.75,34.85 61.556,34.85 61.7,34.994 U3.13@61.7,35.95
BL_EN: R4.2 R5.2 R6.2 R7.1 U4.5 | length 15.6
  Bottom Layer w0.21: U4.5@18.375,53.25 17.775,53.25 17.5,52.975 R7.1@17.5,51.7 17.715,51.485 17.915,51.485 18.5,50.9 18.5,49.85 18.85,49.5 25,49.5 25.335,49.835 25.535,49.835 R5.2@25.75,50.05 R4.2@27.75,50.05 R6.2@27.75,48.7
BL_K: CN2.40 U4.1 | length 21.3
  Signal Layer 1 w0.4: v1(21.175,55.86) 21.175,47.975 v1(21.2,47.95)
  Bottom Layer w0.3: 29.45,41.875 29.74,41.585 CN2.40@29.74,40.05
  Bottom Layer w0.4: U4.1@21.175,55.2 v1(21.175,55.86) ; v1(21.2,47.95) 23.375,47.95 29.45,41.875
BLGND: C9.1 C10.1 C11.1 CN1.47 CN1.49 L3.2 R3.1 R7.2 U4.6 U4.9 | length 20.5
  Bottom Layer w0.3: v1(13.1,51.375) C11.1@13.1,52.75 v1(13.1,54.125) ; v1(13.62,50.75) C10.1@14.425,50.75 ; v1(17.475,53.9) U4.6@18.375,53.9 18.379,53.896 U4.9@19.625,53.896 ; v1(17.5,49.475) R7.2@17.5,50.3 ; v1(19.35,56.5) 19.45,56.4 19.45,55.83 U4.9@19.45,54.9 ; R3.1@19.4,50.725 19.4,51.832 19.35,51.882 v1(19.35,51.95) 19.45,52.05 19.45,52.62 U4.9@19.45,53.55 ; U4.9@20.1,53.55 20.1,52.62 20.1,52.05 v1(20.2,51.95) ; U4.9@20.1,54.9 20.1,55.83 20.1,56.4 v1(20.2,56.5) ; L3.2@27.5,56.925 v1(27.5,57.875) ; CN1.49@48.26,63.147 48.26,61.154 v1(48.275,61.139) ; CN1.47@49.53,63.147 49.53,61.154 v1(49.545,61.139)
  Bottom Layer w0.5: C9.1@23.65,51.075 v1(23.65,52.3)
BLVDD: CN1.45 L1.1 | length 39.9
  Signal Layer 1 w1: v1(25.2,60.025) 25.2,67.425 28.425,70.65 45.29,70.65 v1(50.785,65.155)
  Bottom Layer w0.3: v1(50.785,65.155) v1@50.8,65.14
  Bottom Layer w0.5: L1.1@25.2,58.775 v1(25.2,60.025) ; CN1.45@50.8,63.147 v1@50.8,65.14
CLK: CN2.11 U2.13 | length 41.7
  Bottom Layer w0.21: CN2.11@44.24,40.05 44.24,37.565 49.388,32.417 52.925,28.88 71.762,28.88 76.25,33.368 U2.13@76.25,35.075
DE: CN2.7 U2.19 | length 33.1
  Bottom Layer w0.21: CN2.7@46.24,40.05 46.24,37.941 51.361,32.82 72.62,32.82 73.25,33.45 U2.19@73.25,35.075
DISP: CN2.10 R8.1 R9.2 U2.14 | length 39.9
  Bottom Layer w0.21: CN2.10@44.74,40.05 44.74,37.659 49.808,32.591 52.724,29.675 R8.1@56.625,29.675 R9.2@58.125,29.675 71.963,29.675 75.75,33.462 U2.14@75.75,35.075
G0: CN2.28 U1.13 | length 76.4
  Bottom Layer w0.21: CN2.28@35.74,40.05 35.74,36.562 50.142,22.16 84.432,22.16 85.208,22.16 96.25,33.202 U1.13@96.25,35.075
G1: CN2.27 U1.14 | length 75
  Bottom Layer w0.21: CN2.27@36.24,40.05 36.24,36.656 50.316,22.58 84.258,22.58 85.034,22.58 95.75,33.296 U1.14@95.75,35.075
G2: CN2.26 U1.16 | length 73.3
  Bottom Layer w0.21: CN2.26@36.74,40.05 36.74,36.75 50.49,23 84.86,23 94.75,32.89 U1.16@94.75,35.075
G3: CN2.25 U1.17 | length 71.8
  Bottom Layer w0.21: CN2.25@37.24,40.05 37.24,36.844 50.664,23.42 84.686,23.42 94.25,32.984 U1.17@94.25,35.075
G4: CN2.24 U1.19 | length 70.2
  Bottom Layer w0.21: CN2.24@37.74,40.05 37.74,36.938 50.838,23.84 84.512,23.84 93.25,32.578 U1.19@93.25,35.075
G5: CN2.23 U1.20 | length 68.7
  Bottom Layer w0.21: CN2.23@38.24,40.05 38.24,37.032 51.012,24.26 84.338,24.26 92.75,32.672 U1.20@92.75,35.075
G6: CN2.22 U1.22 | length 67
  Bottom Layer w0.21: CN2.22@38.74,40.05 38.74,37.125 51.186,24.68 84.164,24.68 91.75,32.266 U1.22@91.75,35.075
G7: CN2.21 U1.23 | length 65.6
  Bottom Layer w0.21: CN2.21@39.24,40.05 39.24,37.219 51.359,25.1 83.991,25.1 91.25,32.359 U1.23@91.25,35.075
